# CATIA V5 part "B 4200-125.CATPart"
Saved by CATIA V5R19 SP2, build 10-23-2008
Part number: B 4200-125
Bounding box of the stored display mesh (mm): x -47.487 to 47.487, y -47.487 to 47.487, z 0 to 370
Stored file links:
  C:\Users\Bora\Desktop\3D Katı model\B serisi\B 4200\B 4200-125.CATPart
  C:\Program Files\Dassault Systemes\B19\intel_a\reffiles\standard\MetricThickPitch.txt
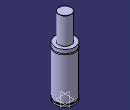
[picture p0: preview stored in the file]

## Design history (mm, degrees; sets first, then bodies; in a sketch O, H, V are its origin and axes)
Body1 (main body)
  Sketch1 on yz-plane, origin (0, 0, 0), H (0, 1, 0), V (0, 0, 1)
    point P1 (47.5, 223.5)
    point P2 (47.5, 218.5)
    point P3 (47.5, 223.5)
    point P6 (47.5, 218.5)
    point P9 (30, 369)
    point P11 (30, 369)
    arc A1 centre (47.5, 221) radius 2.5 from (47.5, 223.5) to (47.5, 218.5) ccw
    line L1 (47.5, 223.5) -> (47.5, 242)
    line L2 (47.5, 13) -> (47.5, 218.5)
    line L3 (43.5, 13) -> (43.5, 8)
    arc A2 centre (29, 369) radius 1 from (30, 369) to (29, 370) ccw
    line L4 (30, 369) -> (30, 242)
    line L5 (47.5, 0) -> (47.5, 8)
    line L6 (29, 370) -> (0, 370)
    point P15 (0, 370)
    line L7 (30, 242) -> (47.5, 242)
    line L8 (0, 0) -> (47.5, 0)
    line L9 (43.5, 13) -> (47.5, 13)
    line L10 (43.5, 8) -> (47.5, 8)
    coincidence: P15 V, P1 P3, P2 P6, P9 P11
    tangency: L6 A2
    horizontal: L7 H, L8 H, L9 H, L10 H
  Shaft1: profile Sketch1, axis Sketch1.V, angle 360
  Sketch2 on face of Shaft1 from Sketch1.L8, origin (0, 0, 0), H (1, 0, 0), V (0, -1, 0)
    point P1 (30, 0)
    distance P1 V = 30
  Hole1: placed by Sketch2, at (30, 0, 0) direction (0, 0, 1), diameter 6.647, depth 13, threaded "M8", thread diameter 8, thread depth 13, pitch 1.25
  CircPattern1: of Hole1, instances 4, angular step 90, axis from xy-plane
